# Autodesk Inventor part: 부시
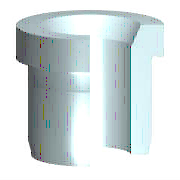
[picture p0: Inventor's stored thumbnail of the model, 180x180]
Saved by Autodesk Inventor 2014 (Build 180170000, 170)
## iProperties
Created: 2009-02
Part Number: 부시
Material: 강, 연강
Description: 압력 맞춤 부시 - 머리 있는 유형
Document SubType Name: Modeling
Standard: ISO 4247
Designer: KYOUNG IL JANG
Standard Revision: 1판 1977-12-15
Standards Organization: ISO
Language: ko-KR
Size Designation: 15
Categories: <MemberInstance><Categories><Category DisplayName="기타 부품" InternalName="5aa15e00-363f-49f2-933f-16f664388e3f" Mnemonic="OTHER"><Category DisplayName="드릴 부싱" Int
Density: 7.86 g/cm^3
Appearance: 강철
Mass: 62.5871 g
Surface Area: 38.4072 cm^2
Volume: 7.96273 cm^3
IsCustomPart: 1
Author: KYOUNG IL JANG
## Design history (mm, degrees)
revolve "본체" stored, may be unused: angle "d12" = 90 deg
body "Solid1"
chamfer "모따기1" distance "d13" = 2 (= KAH); stored, may be unused: angle "d14" = 30 deg (= SEWI), second distance "d19" = 2 (= KAH)
chamfer "모따기2" distance "d15" = 1.5 (= PHH); stored, may be unused: angle "d16" = 15 deg (= ANG), second distance "d20" = 1.5 (= PHH)
sketch "스케치1"
  geometry: L1 (2.5, 11)-(24, 11); L2 (24, 11)-(24, 6); L3 (24, 6)-(-4, 6); L4 (-4, 6)-(-4, 13); L5 (-4, 13)-(0, 13); L6 (0, 13)-(0, 12.304); L7 (-2.619, 0)-(24, 0); L8 (0, 12.304)-(-0.187, 11.425); L9 (2.5, 11)-(1.457, 10.72); L10 (0.4, 10.7)-(1.301, 10.7); L11 (-6.4, 0)-(10.4, 0) reference; L12 (0, -2.2)-(0, 13.2) reference; A1 r 0.6 centre (1.301, 11.3) between (1.301, 10.7) and (1.457, 10.72); A2 r 0.6 centre (0.4, 11.3) between (-0.187, 11.425) and (0.4, 10.7)
  constraints: 20 end point, 5 parallel, 4 point on circle, 4 tangent, 2 centre point, 2 collinear, 2 perpendicular, 1 horizontal, 1 point on line
  dimensions: "d0" = 15 deg angle of L1 L9; "d1" = 12 deg angle of L6 L8; "d2" = 0.6 radius of A2 (= FSRR); "d3" = 0.6 radius of A1 (= FSRR); "d4" = 0.3 distance between parallel lines of L1 L10 (= FST1); "d5" = 0.2 distance edge to line of A2 L6 (= FST2); "d6" = 2.5 distance from line of L1.start L6 (= FSB); "d7" = 12 diameter of L3 L7 (= NND); "d8" = 22 diameter of L1 L7 (= SD2); "d9" = 28 distance between parallel lines of L2 L4 (= NLG); "d10" = 4 distance of L4.end L5.end (= KOH); "d11" = 26 diameter of L5 L7 (= KOD)
other parameters: "NLG" = 28 [user parameter; used in 1 equation term], "NND" = 12 [user parameter; used in 1 equation term], "KOH" = 4 [user parameter; used in 1 equation term], "KOD" = 26 [user parameter; used in 1 equation term], "KAH" = 2 [user parameter; used in 2 equation terms], "SEWI" = 30 deg [user parameter; used in 1 equation term], "ANG" = 15 deg [user parameter; used in 1 equation term], "PHH" = 1.5 [user parameter; used in 2 equation terms], "FST1" = 0.3 [user parameter; used in 1 equation term], "FST2" = 0.2 [user parameter; used in 1 equation term], "FSB" = 2.5 [user parameter; used in 1 equation term], "FSRR" = 0.6 [user parameter; used in 2 equation terms], "SD2" = 22 [user parameter; used in 1 equation term], "d17" = 0, "d18" = 0, "NNDMIN" = 12 [user parameter], "FSH" = 2.1 [user parameter], "NNDMAX" = 15 [user parameter]
